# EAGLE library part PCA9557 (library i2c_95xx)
8bit I2C-Bus-Expander with Reset
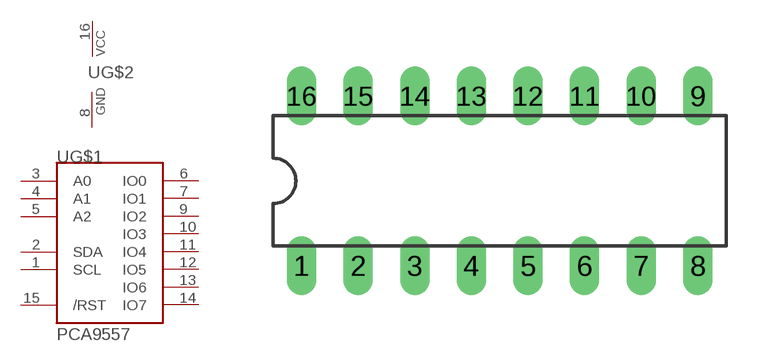
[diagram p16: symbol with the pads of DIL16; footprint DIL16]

Designator prefix -; gates G$1=PCA9557 G$2=PWRN

## PCA9557  [DIL16]
1  G$1:SCL
2  G$1:SDA
3  G$1:A0
4  G$1:A1
5  G$1:A2
6  G$1:IO0
7  G$1:IO1
8  G$2:GND  pwr
9  G$1:IO2
10  G$1:IO3
11  G$1:IO4
12  G$1:IO5
13  G$1:IO6
14  G$1:IO7
15  G$1:/RST
16  G$2:VCC  pwr

## Footprint DIL16 (pad centres in mm)
drill 0.813 long: 1 -8.89,-3.81; 2 -6.35,-3.81; 3 -3.81,-3.81; 4 -1.27,-3.81; 5 1.27,-3.81; 6 3.81,-3.81; 7 6.35,-3.81; 8 8.89,-3.81; 9 8.89,3.81; 10 6.35,3.81; 11 3.81,3.81; 12 1.27,3.81; 13 -1.27,3.81; 14 -3.81,3.81; 15 -6.35,3.81; 16 -8.89,3.81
